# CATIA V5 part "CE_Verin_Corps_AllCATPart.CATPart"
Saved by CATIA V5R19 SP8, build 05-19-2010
Part number: CE7_Vérin_Corps_AllCATPart
Bounding box of the stored display mesh (mm): x -62.451 to -41.451, y -10.5 to 10.5, z -280.567 to 38.433
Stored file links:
  D:\Documents\1_Travail\1 - ac-limoges.fr\ac-limoges.fr\Emmanuel Maynard - STI2D_Turgot\2 -2I2D\1_SEQUENCE_ Tapis_de_course\3- Spécificités\Spé_ITEC\3-Pente\Tapis_TC520B_Pente\CE_Verin_Corps_AllCATPart.CATPart
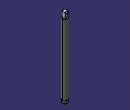
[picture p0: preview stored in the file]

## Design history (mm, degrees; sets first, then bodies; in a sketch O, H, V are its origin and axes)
Body1 (main body)
Body2 "CORPS_ST_250F1VD10.1\\MANIFOLD_SOLID_BREP #15376"
  Solid1: solid without history
Body3 "Chappe_verin.1\\Corps principal"
  Solid2 "Solide.1": solid without history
